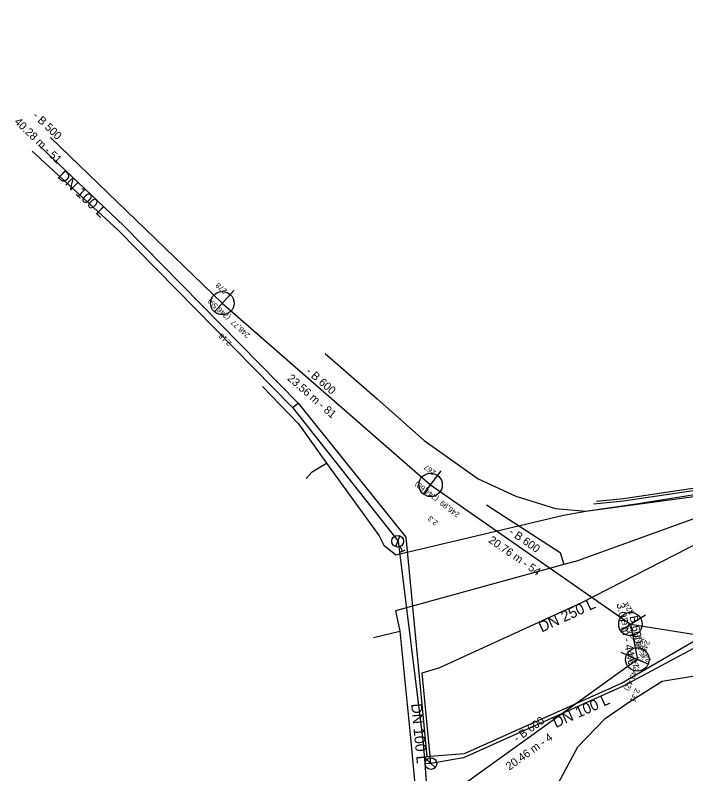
# Model space of a CAD drawing. Extents: x -600636 to -600148, y -1203980 to -1203569.
# Drawn here: x -600636.3 to -600579.1, y -1203804.8 to -1203740.1 of the extents above; entities that cross this region are included whole.
import ezdxf

# ---------------------------------------------------------------- set-up
doc = ezdxf.new("R2010")
doc.units = 0
for name, color, linetype in [('Cetin zam průběh', 7, 'Continuous'), ('EON podzemní NN', 7, 'Continuous'), ('EON podzemní VN', 7, 'Continuous'), ('GasNet NTL', 7, 'Continuous'), ('Implicitní', 7, 'Continuous'), ('VaK Břeclav_kanalizace', 7, 'Continuous'), ('VaK Břeclav_kanalizace_popis', 7, 'Continuous'), ('Vak Břeclav_vodovod', 7, 'Continuous'), ('Vak Břeclav_vodovod_popis', 7, 'Continuous')]:
    doc.layers.add(name, color=color, linetype=linetype)

# ---------------------------------------------------------------- blocks, each defined once
blk = doc.blocks.new('MoSymbol 2')
at = {"layer": 'Implicitní'}
blk.add_line((0, 0.0005), (0, -0.00075), dxfattribs=at)
blk.add_circle((0, 0), 0.0005, dxfattribs=at)
blk = doc.blocks.new('MoSymbol 3')
at = {"layer": 'Implicitní'}
for p, q in [((-0.000225, 0.00095), (0.000225, 0.00095)), ((0, 0.00095), (0, 0.0005)), ((-0.000365, -0.000365), (0.000365, 0.000365))]:
    blk.add_line(p, q, dxfattribs=at)
blk.add_circle((0, 0), 0.0005, dxfattribs=at)

msp = doc.modelspace()

# ---------------------------------------------------------------- linework, layer by layer
at = {"layer": 'Cetin zam průběh'}
for points in [[(-600609.86, -1203768.99), (-600605.43, -1203772.85), (-600601.41, -1203776.4), (-600596.81, -1203779.65), (-600593.61, -1203781.13), (-600590.22, -1203782.2), (-600587.64, -1203782.42)], [(-600615.2, -1203771.78), (-600612.13, -1203774.97), (-600609.75, -1203778.32)], [(-600587.64, -1203782.42), (-600577.59, -1203781.05), (-600571.34, -1203779.9), (-600562.09, -1203773.93), (-600559.42, -1203772.74), (-600558.16, -1203771.94), (-600558.14, -1203772.28)], [(-600611.49, -1203779.63), (-600610.96, -1203779.08), (-600609.75, -1203778.32)], [(-600609.75, -1203778.32), (-600605.26, -1203784.51)], [(-600605.26, -1203784.51), (-600604.87, -1203785.33), (-600603.85, -1203786.14), (-600589.55, -1203782.77), (-600587.64, -1203782.42)], [(-600603.85, -1203786.14), (-600589.55, -1203782.77)], [(-600591.27, -1203810.59), (-600590.6, -1203806.73), (-600588.32, -1203802.51), (-600586.01, -1203800.08), (-600583.97, -1203798.69), (-600581.13, -1203796.91), (-600575.98, -1203796.07), (-600574.075, -1203796.372)]]:
    msp.add_lwpolyline(points, dxfattribs=at)
at = {"layer": 'EON podzemní NN'}
for points in [[(-600525.132, -1203747.742), (-600525.004, -1203747.932), (-600525.449, -1203748.251), (-600531.101, -1203752.305), (-600531.678, -1203753.342), (-600534.216, -1203754.907), (-600539.903, -1203758.664), (-600540.687, -1203759.293), (-600544.438, -1203761.852), (-600545.238, -1203762.368), (-600552.695, -1203767.501), (-600554.501, -1203768.539), (-600555.203, -1203768.985), (-600571.205, -1203779.307), (-600573.331, -1203779.913), (-600584.423, -1203781.578), (-600586.99, -1203781.825)], [(-600525.297, -1203747.856), (-600525.279, -1203747.883), (-600531.254, -1203752.169), (-600531.757, -1203753.151), (-600534.324, -1203754.739), (-600540.021, -1203758.502), (-600540.809, -1203758.243), (-600540.807, -1203759.133), (-600544.548, -1203761.686), (-600545.191, -1203761.339), (-600545.348, -1203762.202), (-600552.801, -1203767.331), (-600554.605, -1203768.367), (-600555.135, -1203768.259), (-600555.311, -1203768.817), (-600571.289, -1203779.123), (-600573.373, -1203779.717), (-600584.447, -1203781.38), (-600586.729, -1203781.599)]]:
    msp.add_lwpolyline(points, dxfattribs=at)
at = {"layer": 'EON podzemní VN'}
msp.add_lwpolyline([(-600587.683, -1203782.424), (-600583.35, -1203781.8), (-600578.39, -1203781.01), (-600575.54, -1203780.47), (-600571.28, -1203779.25), (-600564.47, -1203775), (-600557.37, -1203770.49), (-600546.85, -1203763.19), (-600538.93, -1203757.78), (-600533.07, -1203753.94), (-600532.42, -1203753.34), (-600525.77, -1203761.6), (-600524.04, -1203762.18), (-600520.34, -1203759.69), (-600515.99, -1203756.58), (-600509.828, -1203765.1), (-600508.705, -1203765.014), (-600506.819, -1203763.668), (-600505.22, -1203765.813), (-600504.7, -1203765.596)], dxfattribs=at)
at = {"layer": 'GasNet NTL'}
for points in [[(-600486.68, -1203722.48), (-600489.25, -1203724.39), (-600497.78, -1203730.73), (-600501.03, -1203733.15), (-600504.95, -1203736.06), (-600509.64, -1203739.28), (-600520.2, -1203746.52), (-600535.72, -1203757.18), (-600536.81, -1203757.93), (-600541.8, -1203761.35), (-600546.79, -1203764.85), (-600559, -1203773.38), (-600566.88, -1203778.88), (-600575.24, -1203781.91), (-600588.36, -1203786.65), (-600589.51, -1203786.96)], [(-600596.108, -1203781.888), (-600589.83, -1203785.95), (-600589.51, -1203786.96)], [(-600589.51, -1203786.96), (-600603.87, -1203790.9), (-600603.51, -1203792.65), (-600602.6, -1203801.75), (-600602.09, -1203807.23), (-600602.04, -1203807.76), (-600601.82, -1203810.05), (-600601.01, -1203818.68), (-600600.79, -1203823.05), (-600600.33, -1203831.768)], [(-600605.74, -1203793.2), (-600603.51, -1203792.65)]]:
    msp.add_lwpolyline(points, dxfattribs=at)
at = {"layer": 'VaK Břeclav_kanalizace'}
for p, q in [((-600633.26, -1203750.574), (-600618.628, -1203764.69)), ((-600618.628, -1203764.69), (-600600.876, -1203780.176)), ((-600600.876, -1203780.176), (-600583.84, -1203792.047)), ((-600583.84, -1203792.047), (-600583.255, -1203795.061)), ((-600583.84, -1203792.047), (-600558.458, -1203796.062)), ((-600583.255, -1203795.061), (-600599.868, -1203807.001))]:
    msp.add_line(p, q, dxfattribs=at)
at = {"layer": 'Vak Břeclav_vodovod'}
for p, q in [((-600612.656, -1203773.597), (-600612.162, -1203773.201)), ((-600612.656, -1203773.597), (-600603.646, -1203784.964)), ((-600601.355, -1203803.909), (-600600.849, -1203803.933))]:
    msp.add_line(p, q, dxfattribs=at)
for points in [[(-600612.162, -1203773.201), (-600627.017, -1203758.086), (-600634.211, -1203751.28)], [(-600634.836, -1203751.743), (-600627.511, -1203758.482), (-600612.656, -1203773.597)], [(-600612.162, -1203773.201), (-600602.995, -1203784.637), (-600601.189, -1203803.343), (-600600.899, -1203803.294), (-600597.986, -1203803.077), (-600584.599, -1203797.079), (-600575.117, -1203791.572), (-600573.857, -1203790.834), (-600573.636, -1203791.26), (-600573.583, -1203791.689)], [(-600600.849, -1203803.933), (-600600.899, -1203803.294), (-600601.584, -1203796.186), (-600600.078, -1203795.751), (-600587.99, -1203790.2), (-600577.783, -1203784.972), (-600568.695, -1203781.296)], [(-600603.646, -1203784.964), (-600601.496, -1203802.202), (-600601.355, -1203803.909)], [(-600574.494, -1203791.995), (-600584.471, -1203797.336), (-600598.082, -1203803.451), (-600600.849, -1203803.933)], [(-600601.355, -1203803.909), (-600600.518, -1203815.976), (-600600.505, -1203816.572)]]:
    msp.add_lwpolyline(points, dxfattribs=at)

# ---------------------------------------------------------------- block references
at = {"layer": 'VaK Břeclav_kanalizace'}
for p, xscale, yscale, rotation in [((-600618.628, -1203764.69), 1999.7500312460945, 1999.750031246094, 137.46399104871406), ((-600600.876, -1203780.176), 1999.750031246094, 1999.7500312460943, 142.4307789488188), ((-600583.84, -1203792.047), 1999.7500312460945, 1999.750031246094, 122.28574105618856), ((-600583.255, -1203795.061), 1999.750031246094, 1999.750031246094, -112.84231542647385)]:
    msp.add_blockref('MoSymbol 2', p, dxfattribs=dict(at, xscale=xscale, yscale=yscale, rotation=rotation))
at = {"layer": 'Vak Břeclav_vodovod'}
for name, p, xscale, yscale, rotation in [('MoSymbol 3', (-600603.682, -1203784.981), 999.8750156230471, 999.8750156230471, -154.96493830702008), ('MoSymbol 2', (-600600.849, -1203803.933), 999.875015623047, 999.8750156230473, -134.120714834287)]:
    msp.add_blockref(name, p, dxfattribs=dict(at, xscale=xscale, yscale=yscale, rotation=rotation))

# ---------------------------------------------------------------- texts
at = {"layer": 'VaK Břeclav_kanalizace_popis'}
for s, height, rotation, p in [('- B 500', 0.6824, 316.02788, (-600634.831, -1203748.776)), ('40.28 m - 51', 0.68241, 316.02788, (-600636.404, -1203749.289)), ('278', 0.4549, 137.46399, (-600618.173, -1203763.607)), ('248,77  (246,59)', 0.45494, 137.46399, (-600616.229, -1203767.373)), ('2.18', 0.4549, 137.46399, (-600617.786, -1203768.045)), ('23.56 m - 81', 0.68241, 318.90011, (-600613.139, -1203771.184)), ('- B 600', 0.6824, 318.90011, (-600611.54, -1203770.591)), ('267', 0.4549, 142.43078, (-600600.387, -1203779.052)), ('246,99  (244,69)', 0.45494, 142.43078, (-600598.349, -1203782.646)), ('2.3', 0.4549, 142.43078, (-600600.195, -1203783.326)), ('- B 600', 0.6824, 325.13111, (-600594.263, -1203784.319)), ('20.76 m - 54', 0.68241, 325.13111, (-600596, -1203785.023)), ('3.07 m - 44.6', 0.68241, 280.98676, (-600585.028, -1203790.307)), ('22a', 0.4549, 122.28574, (-600583.522, -1203791.05)), ('- B 600', 0.6824, 280.98676, (-600584.018, -1203790.849)), ('245,68  (243,6)', 0.45494, 122.28574, (-600582.055, -1203795.12)), ('245,73  (243,42)', 0.45494, 247.15768, (-600582.573, -1203793.369)), ('257', 0.4549, 247.15768, (-600583.015, -1203792.992)), ('2.08', 0.4549, 122.28574, (-600583.068, -1203795.617)), ('2.31', 0.4549, 247.15768, (-600583.418, -1203797.475)), ('- B 600', 0.6824, 35.70534, (-600593.488, -1203802.133)), ('20.46 m - 4', 0.68241, 35.70534, (-600594.158, -1203804.538))]:
    msp.add_text(s, height=height, rotation=rotation, dxfattribs=at).set_placement(p)
at = {"layer": 'Vak Břeclav_vodovod_popis'}
for s, rotation, p in [('DN 100 L', 316.58843, (-600632.726, -1203753.938)), ('DN 250 L', 24.66533, (-600591.407, -1203792.77)), ('DN 100 L', 24.19291, (-600590.205, -1203800.91)), ('DN 100 L', 275.51462, (-600602.537, -1203798.85))]:
    msp.add_text(s, height=0.9099, rotation=rotation, dxfattribs=at).set_placement(p)

doc.saveas('drawing.dxf')
